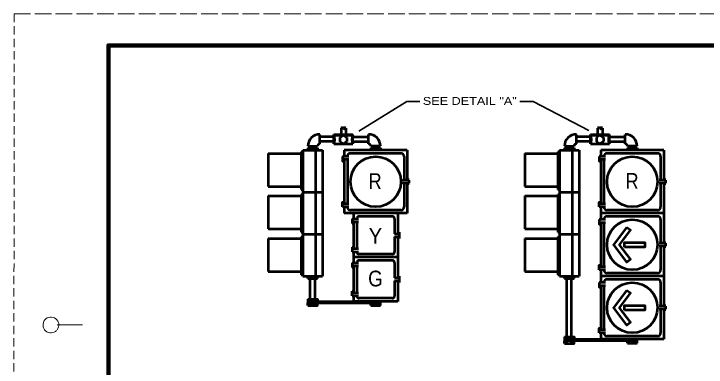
# Model space of a CAD drawing. Extents: x -295 to 385, y -102 to 338.
# Drawn here: x -295.3 to -75.4, y 226.3 to 338.4 of the extents above; entities that cross this region are included whole.
import ezdxf
from ezdxf.enums import TextEntityAlignment as Align

# ---------------------------------------------------------------- set-up
doc = ezdxf.new("R2010")
doc.units = 0
doc.header["$LTSCALE"] = 0.88
doc.linetypes.add('LONG_DASHED', pattern=[7.5, 6, -1.5])
doc.linetypes.add('MEDIUM_DASHED', pattern=[4.5, 3, -1.5])
doc.layers.add('1', color=7, linetype='Continuous', lineweight=53)
doc.layers.add('61', color=7, linetype='Continuous', lineweight=35)

msp = doc.modelspace()

# ---------------------------------------------------------------- linework, layer by layer
at = {"layer": '1', "linetype": 'MEDIUM_DASHED', "lineweight": 13}
msp.add_line((-295.2093, 338.4444), (-295.2693, -101.5956), dxfattribs=at)
at = {"layer": '1', "lineweight": 35}
for p, q in [((-170.5093, 310.6583), (-185.6989, 301.2522)), ((-170.5093, 310.6583), (-166.3502, 310.6583)), ((-134.5243, 310.6583), (-130.3653, 310.6583)), ((-130.3653, 310.6583), (-112.6441, 301.4331))]:
    msp.add_line(p, q, dxfattribs=at)
at = {"layer": '1'}
for p, q in [((-191.3669, 302.1533), (-191.3669, 300.1533)), ((-189.8669, 302.1533), (-189.8669, 300.1533)), ((-109.8669, 302.1533), (-109.8669, 300.1533)), ((-108.3669, 302.1533), (-108.3669, 300.1533)), ((-198.1169, 297.1533), (-198.1169, 300.1533)), ((-193.6169, 299.4033), (-198.1169, 299.4033)), ((-193.6169, 300.1533), (-187.6169, 300.1533)), ((-193.6169, 299.9033), (-187.6169, 299.9033)), ((-190.6169, 299.9033), (-191.7419, 299.2283)), ((-191.7419, 299.2283), (-191.7419, 297.8282)), ((-190.6169, 299.9033), (-189.4919, 299.2283)), ((-189.4919, 299.2283), (-189.4919, 297.9282)), ((-187.6169, 297.1533), (-187.6169, 300.1533)), ((-187.6068, 299.4117), (-182.6068, 299.4117)), ((-182.6068, 297.1617), (-182.6068, 300.1617)), ((-116.6169, 297.1533), (-116.6169, 300.1533)), ((-112.1169, 299.4033), (-116.6169, 299.4033)), ((-112.1169, 300.1533), (-106.1169, 300.1533)), ((-112.1169, 299.9033), (-106.1169, 299.9033)), ((-109.1169, 299.9033), (-110.2419, 299.2283)), ((-110.2419, 299.2283), (-110.2419, 297.8282)), ((-109.1169, 299.9033), (-107.9919, 299.2283)), ((-107.9919, 299.2283), (-107.9919, 297.9282)), ((-106.1169, 297.1533), (-106.1169, 300.1533)), ((-106.1068, 299.4117), (-101.1068, 299.4117)), ((-101.1068, 297.1617), (-101.1068, 300.1617)), ((-193.6169, 297.9033), (-198.1169, 297.9033)), ((-193.6169, 297.1533), (-187.6169, 297.1533)), ((-191.7419, 297.8282), (-190.6169, 297.1533)), ((-189.4919, 297.9282), (-190.6169, 297.1533)), ((-187.6068, 297.9117), (-182.6068, 297.9117)), ((-112.1169, 297.9033), (-116.6169, 297.9033)), ((-112.1169, 297.1533), (-106.1169, 297.1533)), ((-110.2419, 297.8282), (-109.1169, 297.1533)), ((-107.9919, 297.9282), (-109.1169, 297.1533)), ((-106.1068, 297.9117), (-101.1068, 297.9117)), ((-203.9919, 294.6533), (-203.9919, 282.6533)), ((-203.9919, 294.6533), (-203.4919, 294.6533)), ((-203.4919, 295.1533), (-203.4919, 255.1532)), ((-203.4919, 295.1533), (-197.2419, 295.1533)), ((-201.8669, 296.4033), (-198.8669, 296.4033)), ((-201.8669, 295.9033), (-201.8669, 295.1533)), ((-201.8669, 295.9033), (-198.8669, 295.9033)), ((-201.1169, 296.4033), (-201.1169, 295.1533)), ((-199.6169, 296.4033), (-199.6169, 295.1533)), ((-199.4919, 294.9033), (-199.4919, 255.4032)), ((-198.8669, 295.9033), (-198.8669, 295.1533)), ((-197.2419, 295.1533), (-197.2419, 255.1532)), ((-170.3568, 295.1617), (-190.3568, 295.1617)), ((-190.3568, 295.1617), (-190.3568, 293.1617)), ((-178.8568, 296.4117), (-181.8568, 296.4117)), ((-181.8568, 295.9117), (-181.8568, 295.1617)), ((-178.8568, 295.9117), (-181.8568, 295.9117)), ((-181.1068, 296.4117), (-181.1068, 295.1617)), ((-179.6068, 296.4117), (-179.6068, 295.1617)), ((-178.8568, 295.9117), (-178.8568, 295.1617)), ((-170.3568, 295.1617), (-170.3568, 285.6617)), ((-122.4919, 294.6533), (-122.4919, 282.6533)), ((-122.4919, 294.6533), (-121.9919, 294.6533)), ((-121.9919, 295.1533), (-121.9919, 255.1532)), ((-121.9919, 295.1533), (-115.7419, 295.1533)), ((-120.3669, 296.4033), (-117.3669, 296.4033)), ((-120.3669, 295.9033), (-120.3669, 295.1533)), ((-120.3669, 295.9033), (-117.3669, 295.9033)), ((-119.6169, 296.4033), (-119.6169, 295.1533)), ((-118.1169, 296.4033), (-118.1169, 295.1533)), ((-117.9919, 294.9033), (-117.9919, 255.4032)), ((-117.3669, 295.9033), (-117.3669, 295.1533)), ((-115.7419, 295.1533), (-115.7419, 255.1532)), ((-88.8568, 295.1617), (-108.8568, 295.1617)), ((-108.8568, 295.1617), (-108.8568, 293.1617)), ((-97.3568, 296.4117), (-100.3568, 296.4117)), ((-100.3568, 295.9117), (-100.3568, 295.1617)), ((-97.3568, 295.9117), (-100.3568, 295.9117)), ((-99.6068, 296.4117), (-99.6068, 295.1617)), ((-98.1068, 296.4117), (-98.1068, 295.1617)), ((-97.3568, 295.9117), (-97.3568, 295.1617)), ((-88.8568, 295.1617), (-88.8568, 285.6617)), ((-214.4919, 294.1533), (-203.9919, 294.1533)), ((-214.4919, 294.1533), (-214.4919, 283.6533)), ((-188.8568, 293.1617), (-190.8568, 293.1617)), ((-172.3568, 294.1617), (-188.3568, 294.1617)), ((-171.3568, 293.1617), (-171.3568, 285.6617)), ((-132.9919, 294.1533), (-122.4919, 294.1533)), ((-132.9919, 294.1533), (-132.9919, 283.6533)), ((-107.3568, 293.1617), (-109.3568, 293.1617)), ((-90.8568, 294.1617), (-106.8568, 294.1617)), ((-89.8568, 293.1617), (-89.8568, 285.6617)), ((-188.8568, 292.1617), (-190.8568, 292.1617)), ((-190.3568, 292.1617), (-190.3568, 278.1617)), ((-189.3568, 292.1617), (-189.3568, 278.1617)), ((-107.3568, 292.1617), (-109.3568, 292.1617)), ((-108.8568, 292.1617), (-108.8568, 278.1617)), ((-107.8568, 292.1617), (-107.8568, 278.1617)), ((-170.1068, 286.1617), (-170.1068, 285.6617)), ((-88.6068, 286.1617), (-88.6068, 285.6617)), ((-214.4919, 283.6533), (-203.9919, 283.6533)), ((-169.8568, 285.6617), (-171.8568, 285.6617)), ((-169.8568, 284.6617), (-171.8568, 284.6617)), ((-171.3568, 284.6617), (-171.3568, 277.1617)), ((-170.3568, 284.6617), (-170.3568, 275.1617)), ((-170.1068, 284.6617), (-170.1068, 284.1617)), ((-169.8568, 285.6617), (-169.8568, 284.6617)), ((-132.9919, 283.6533), (-122.4919, 283.6533)), ((-88.3568, 285.6617), (-90.3568, 285.6617)), ((-88.3568, 284.6617), (-90.3568, 284.6617)), ((-89.8568, 284.6617), (-89.8568, 277.1617)), ((-88.8568, 284.6617), (-88.8568, 275.1617)), ((-88.6068, 284.6617), (-88.6068, 284.1617)), ((-88.3568, 285.6617), (-88.3568, 284.6617)), ((-203.9919, 282.6533), (-203.4919, 282.6533)), ((-203.4919, 281.8232), (-197.2419, 281.8232)), ((-122.4919, 282.6533), (-121.9919, 282.6533)), ((-121.9919, 281.8232), (-115.7419, 281.8232)), ((-214.4919, 280.6533), (-203.9919, 280.6533)), ((-214.4919, 280.6533), (-214.4919, 270.1533)), ((-203.9919, 281.1533), (-203.9919, 269.1533)), ((-203.9919, 281.1533), (-203.4919, 281.1533)), ((-132.9919, 280.6533), (-122.4919, 280.6533)), ((-132.9919, 280.6533), (-132.9919, 270.1533)), ((-122.4919, 281.1533), (-122.4919, 269.1533)), ((-122.4919, 281.1533), (-121.9919, 281.1533)), ((-188.8568, 278.1617), (-190.8568, 278.1617)), ((-188.8568, 277.1617), (-190.8568, 277.1617)), ((-190.3568, 277.1617), (-190.3568, 275.1617)), ((-107.3568, 278.1617), (-109.3568, 278.1617)), ((-107.3568, 277.1617), (-109.3568, 277.1617)), ((-108.8568, 277.1617), (-108.8568, 275.1617)), ((-170.3568, 275.1617), (-190.3568, 275.1617)), ((-172.3568, 276.1617), (-188.3568, 276.1617)), ((-187.3568, 275.1617), (-187.3568, 273.4117)), ((-173.3568, 275.1617), (-173.3568, 268.6617)), ((-88.8568, 275.1617), (-108.8568, 275.1617)), ((-108.8568, 275.1617), (-108.8568, 273.1617)), ((-90.8568, 276.1617), (-106.8568, 276.1617)), ((-88.8568, 275.1617), (-88.8568, 265.6617)), ((-187.8568, 273.4117), (-185.8568, 273.4117)), ((-187.8568, 273.4117), (-187.8568, 271.9117)), ((-175.1068, 274.1617), (-185.6068, 274.1617)), ((-174.3568, 273.4117), (-174.3568, 268.6617)), ((-107.3568, 273.1617), (-109.3568, 273.1617)), ((-90.8568, 274.1617), (-106.8568, 274.1617)), ((-89.8568, 273.1617), (-89.8568, 265.6617)), ((-187.8568, 272.4117), (-185.8568, 272.4117)), ((-187.8568, 271.9117), (-187.3568, 271.9117)), ((-187.3568, 272.4117), (-187.3568, 263.9117)), ((-186.3568, 272.4117), (-186.3568, 263.9117)), ((-107.3568, 272.1617), (-109.3568, 272.1617)), ((-108.8568, 272.1617), (-108.8568, 258.1617)), ((-107.8568, 272.1617), (-107.8568, 258.1617)), ((-214.4919, 270.1533), (-203.9919, 270.1533)), ((-203.9919, 269.1533), (-203.4919, 269.1533)), ((-203.4919, 268.4832), (-197.2419, 268.4832)), ((-174.3568, 268.6617), (-172.8568, 268.6617)), ((-172.8568, 269.1617), (-172.8568, 267.1617)), ((-132.9919, 270.1533), (-122.4919, 270.1533)), ((-122.4919, 269.1533), (-121.9919, 269.1533)), ((-121.9919, 268.4832), (-115.7419, 268.4832)), ((-214.4919, 267.1533), (-214.1732, 267.1667)), ((-214.4919, 267.1533), (-203.9919, 267.1533)), ((-214.4919, 267.1533), (-214.4919, 256.6533)), ((-203.9919, 267.6533), (-203.9919, 255.6532)), ((-203.9919, 267.6533), (-203.4919, 267.6533)), ((-174.3568, 267.6617), (-172.8568, 267.6617)), ((-174.3568, 267.6617), (-174.3568, 262.9117)), ((-173.3568, 267.6617), (-173.3568, 254.6617)), ((-132.9919, 267.1533), (-132.6732, 267.1667)), ((-132.9919, 267.1533), (-122.4919, 267.1533)), ((-132.9919, 267.1533), (-132.9919, 256.6533)), ((-122.4919, 267.6533), (-122.4919, 255.6532)), ((-122.4919, 267.6533), (-121.9919, 267.6533)), ((-88.6068, 266.1617), (-88.6068, 265.6617)), ((-187.8568, 264.4117), (-187.8568, 262.9117)), ((-187.8568, 264.4117), (-187.3568, 264.4117)), ((-187.8568, 263.9117), (-185.8568, 263.9117)), ((-88.3568, 265.6617), (-90.3568, 265.6617)), ((-88.3568, 264.6617), (-90.3568, 264.6617)), ((-89.8568, 264.6617), (-89.8568, 257.1617)), ((-88.8568, 264.6617), (-88.8568, 255.1617)), ((-88.6068, 264.6617), (-88.6068, 264.1617)), ((-88.3568, 265.6617), (-88.3568, 264.6617)), ((-187.8568, 262.9117), (-185.8568, 262.9117)), ((-187.3568, 262.9117), (-187.3568, 259.4117)), ((-175.1068, 262.1617), (-185.6068, 262.1617)), ((-173.3568, 261.1617), (-187.3568, 261.1617)), ((-175.1068, 260.1617), (-185.6068, 260.1617)), ((-187.8568, 259.4117), (-185.8568, 259.4117)), ((-187.8568, 259.4117), (-187.8568, 257.9117)), ((-187.8568, 258.4117), (-185.8568, 258.4117)), ((-187.8568, 257.9117), (-187.3568, 257.9117)), ((-187.3568, 258.4117), (-187.3568, 249.9117)), ((-186.3568, 258.4117), (-186.3568, 249.9117)), ((-174.3568, 259.4117), (-174.3568, 254.6617)), ((-107.3568, 258.1617), (-109.3568, 258.1617)), ((-214.4919, 256.6533), (-203.9919, 256.6533)), ((-203.9919, 255.6532), (-203.4919, 255.6532)), ((-203.4919, 255.1532), (-197.2419, 255.1532)), ((-201.8669, 254.4079), (-201.8669, 255.1579)), ((-198.8669, 254.4079), (-198.8669, 255.1579)), ((-172.8568, 255.1617), (-172.8568, 253.1617)), ((-132.9919, 256.6533), (-122.4919, 256.6533)), ((-122.4919, 255.6532), (-121.9919, 255.6532)), ((-121.9919, 255.1532), (-115.7419, 255.1532)), ((-120.3669, 254.4079), (-120.3669, 255.1579)), ((-117.3669, 254.4079), (-117.3669, 255.1579)), ((-107.3568, 257.1617), (-109.3568, 257.1617)), ((-108.8568, 257.1617), (-108.8568, 255.1617)), ((-88.8568, 255.1617), (-108.8568, 255.1617)), ((-108.8568, 255.1617), (-108.8568, 253.1617)), ((-90.8568, 256.1617), (-106.8568, 256.1617)), ((-88.8568, 255.1617), (-88.8568, 245.6617)), ((-201.8669, 254.4079), (-198.8669, 254.4079)), ((-174.3568, 254.6617), (-172.8568, 254.6617)), ((-174.3568, 253.6617), (-172.8568, 253.6617)), ((-174.3568, 253.6617), (-174.3568, 248.9117)), ((-173.3568, 253.6617), (-173.3568, 247.1617)), ((-120.3669, 254.4079), (-117.3669, 254.4079)), ((-107.3568, 253.1617), (-109.3568, 253.1617)), ((-90.8568, 254.1617), (-106.8568, 254.1617)), ((-89.8568, 253.1617), (-89.8568, 245.6617)), ((-107.3568, 252.1617), (-109.3568, 252.1617)), ((-108.8568, 252.1617), (-108.8568, 238.1617)), ((-107.8568, 252.1617), (-107.8568, 238.1617)), ((-187.8568, 248.9117), (-187.8568, 250.4117)), ((-187.8568, 250.4117), (-187.3568, 250.4117)), ((-187.8568, 249.9117), (-185.8568, 249.9117)), ((-187.8568, 248.9117), (-185.8568, 248.9117)), ((-187.3568, 248.9117), (-187.3568, 247.1617)), ((-178.8568, 247.0617), (-201.8669, 247.0617)), ((-201.8669, 245.8369), (-201.8669, 246.6627)), ((-178.8568, 246.6617), (-201.8669, 246.6617)), ((-201.1169, 247.8874), (-201.1169, 247.0617)), ((-201.1169, 245.8369), (-201.1169, 246.6627)), ((-199.6169, 247.8874), (-199.6169, 247.0617)), ((-199.6169, 245.8369), (-199.6169, 246.6627)), ((-173.3568, 247.1617), (-187.3568, 247.1617)), ((-175.1068, 248.1617), (-185.6068, 248.1617)), ((-181.8568, 245.9117), (-181.8568, 246.6617)), ((-181.1068, 245.9117), (-181.1068, 246.6617)), ((-179.6068, 245.9117), (-179.6068, 246.6617)), ((-178.8568, 245.9117), (-178.8568, 247.1617)), ((-181.8568, 245.9117), (-178.8568, 245.9117)), ((-88.3568, 245.6617), (-90.3568, 245.6617)), ((-88.3568, 244.6617), (-90.3568, 244.6617)), ((-89.8568, 244.6617), (-89.8568, 237.1617)), ((-88.8568, 244.6617), (-88.8568, 235.1617)), ((-88.6068, 246.1617), (-88.6068, 245.6617)), ((-88.6068, 244.6617), (-88.6068, 244.1617)), ((-88.3568, 245.6617), (-88.3568, 244.6617)), ((-107.3568, 238.1617), (-109.3568, 238.1617)), ((-119.6169, 235.8874), (-119.6169, 235.0617)), ((-118.1169, 235.8874), (-118.1169, 235.0617)), ((-107.3568, 237.1617), (-109.3568, 237.1617)), ((-108.8568, 237.1617), (-108.8568, 235.1617)), ((-90.8568, 236.1617), (-106.8568, 236.1617)), ((-97.3568, 235.0617), (-120.3669, 235.0617)), ((-120.3669, 233.8369), (-120.3669, 234.6627)), ((-97.3568, 234.6617), (-120.3669, 234.6617)), ((-119.6169, 233.8369), (-119.6169, 234.6627)), ((-118.1169, 233.8369), (-118.1169, 234.6627)), ((-88.8568, 235.1617), (-108.8568, 235.1617)), ((-100.3568, 233.9117), (-100.3568, 234.6617)), ((-100.3568, 233.9117), (-97.3568, 233.9117)), ((-99.6068, 233.9117), (-99.6068, 234.6617)), ((-98.1068, 233.9117), (-98.1068, 234.6617)), ((-97.3568, 233.9117), (-97.3568, 235.1617))]:
    msp.add_line(p, q, dxfattribs=at)
for points in [[(-193.6169, 297.1533), (-193.6169, 299.9033), (-193.6169, 300.1533)], [(-112.1169, 297.1533), (-112.1169, 299.9033), (-112.1169, 300.1533)], [(-190.8568, 293.1617), (-190.8568, 291.6617), (-190.3568, 291.6617)], [(-109.3568, 293.1617), (-109.3568, 291.6617), (-108.8568, 291.6617)], [(-190.8568, 277.1617), (-190.8568, 278.6617), (-190.3568, 278.6617)], [(-109.3568, 277.1617), (-109.3568, 278.6617), (-108.8568, 278.6617)], [(-109.3568, 273.1617), (-109.3568, 271.6617), (-108.8568, 271.6617)], [(-109.3568, 257.1617), (-109.3568, 258.6617), (-108.8568, 258.6617)], [(-201.1169, 247.9079), (-201.1169, 254.4079), (-201.1169, 255.1579)], [(-199.6169, 247.9079), (-199.6169, 254.4079), (-199.6169, 255.1579)], [(-119.6169, 235.8874), (-119.6169, 254.4079), (-119.6169, 255.1579)], [(-118.1169, 235.8874), (-118.1169, 254.4079), (-118.1169, 255.1579)], [(-109.3568, 253.1617), (-109.3568, 251.6617), (-108.8568, 251.6617)], [(-201.8669, 247.8874), (-198.8669, 247.8874), (-198.8669, 247.0617)], [(-201.8669, 247.8874), (-201.8669, 247.0617), (-201.8669, 246.6617)], [(-201.8669, 245.8369), (-198.8669, 245.8369), (-198.8669, 246.6627)], [(-109.3568, 237.1617), (-109.3568, 238.6617), (-108.8568, 238.6617)], [(-120.3669, 235.8874), (-117.3669, 235.8874), (-117.3669, 235.0617)], [(-120.3669, 235.8874), (-120.3669, 235.0617), (-120.3669, 234.6617)], [(-120.3669, 233.8369), (-117.3669, 233.8369), (-117.3669, 234.6627)]]:
    msp.add_lwpolyline(points, dxfattribs=at)
for points in [[(-100.6591, 270.6617), (-104.8478, 265.1617), (-100.6555, 259.6617), (-99.4626, 260.571), (-102.9622, 265.1622), (-99.4658, 269.7529)], [(-101.3478, 264.4117), (-101.3478, 265.9117), (-94.8478, 265.9117), (-94.8478, 264.4117)], [(-100.6591, 250.6617), (-104.8478, 245.1617), (-100.6555, 239.6617), (-99.4626, 240.571), (-102.9622, 245.1622), (-99.4658, 249.7529)], [(-101.3478, 244.4117), (-101.3478, 245.9117), (-94.8478, 245.9117), (-94.8478, 244.4117)]]:
    msp.add_lwpolyline(points, close=True, dxfattribs=at)
for centre in [(-180.3478, 285.1636), (-98.8478, 285.1636), (-98.8478, 265.1636), (-98.8478, 245.1636)]:
    msp.add_circle(centre, 8, dxfattribs=at)
for centre, radius, start, end in [((-190.9919, 301.803), 0.5131, 43.04811, 136.95189), ((-190.2419, 301.803), 0.5131, 43.04811, 136.95189), ((-190.2419, 302.5), 0.5131, 223.04811, 316.95189), ((-109.4919, 301.803), 0.5131, 43.04811, 136.95189), ((-108.7419, 301.803), 0.5131, 43.04811, 136.95189), ((-108.7419, 302.5), 0.5131, 223.04811, 316.95189), ((-198.2748, 296.5611), 3.5956, 87.48391, 182.51609), ((-196.6689, 298.5283), 3.3474, 335.74702, 24.25298), ((-184.5956, 298.5283), 3.3474, 155.74702, 204.25298), ((-182.449, 296.5695), 3.5956, 357.48391, 92.51609), ((-116.7748, 296.5611), 3.5956, 87.48391, 182.51609), ((-115.1689, 298.5283), 3.3474, 335.74702, 24.25298), ((-103.0956, 298.5283), 3.3474, 155.74702, 204.25298), ((-100.949, 296.5695), 3.5956, 357.48391, 92.51609), ((-198.1537, 296.44), 0.7142, 87.04875, 182.95125), ((-182.5701, 296.4484), 0.7142, 357.04875, 92.95125), ((-116.6537, 296.44), 0.7142, 87.04875, 182.95125), ((-101.0701, 296.4484), 0.7142, 357.04875, 92.95125), ((-188.3568, 293.1617), 1, 90, 180), ((-172.3568, 293.1617), 1, 0, 90), ((-106.8568, 293.1617), 1, 90, 180), ((-90.8568, 293.1617), 1, 0, 90), ((-188.3568, 277.1617), 1, 180, 270), ((-172.3568, 277.1617), 1, 270, 0), ((-106.8568, 277.1617), 1, 180, 270), ((-90.8568, 277.1617), 1, 270, 0), ((-185.6068, 273.4117), 0.75, 90, 180), ((-175.1068, 273.4117), 0.75, 0, 90), ((-106.8568, 273.1617), 1, 90, 180), ((-90.8568, 273.1617), 1, 0, 90), ((-185.6068, 262.9117), 0.75, 180, 270), ((-175.1068, 262.9117), 0.75, 270, 0), ((-185.6068, 259.4117), 0.75, 90, 180), ((-175.1068, 259.4117), 0.75, 0, 90), ((-106.8568, 257.1617), 1, 180, 270), ((-90.8568, 257.1617), 1, 270, 0), ((-106.8568, 253.1617), 1, 90, 180), ((-90.8568, 253.1617), 1, 0, 90), ((-185.6068, 248.9117), 0.75, 180, 270), ((-175.1068, 248.9117), 0.75, 270, 0), ((-106.8568, 237.1617), 1, 180, 270), ((-90.8568, 237.1617), 1, 270, 0)]:
    msp.add_arc(centre, radius, start, end, dxfattribs=at)
at = {"layer": '61', "linetype": 'LONG_DASHED', "lineweight": 13}
msp.add_line((-295.2093, 338.4444), (384.8107, 338.4444), dxfattribs=at)
at = {"layer": '61', "lineweight": 13}
msp.add_line((-281.4893, 239.6844), (-273.5093, 239.7044), dxfattribs=at)
at = {"layer": '61', "lineweight": 158}
msp.add_lwpolyline([(373.8307, 328.4444), (-265.2093, 328.4444), (-265.2093, -91.5756)], dxfattribs=at)
at = {"layer": '61', "lineweight": 13}
msp.add_arc((-283.5116, 239.6857), 2.5, 323.13009, 316.23216, dxfattribs=at)

# ---------------------------------------------------------------- texts
at = {"layer": '1', "width": 1.2}
msp.add_text('SEE DETAIL "A"', height=2.5, dxfattribs=at).set_placement((-150.4665, 309.5478), align=Align.CENTER)
at = {"layer": '1'}
for s, width, p in [('R', 0.85, (-182.5741, 282.8628)), ('R', 0.85, (-100.9668, 282.9015)), ('Y', 0.95, (-182.559, 265.4451)), ('G', 0.9, (-182.754, 251.9267))]:
    msp.add_text(s, height=5, dxfattribs=dict(at, width=width)).set_placement(p)

doc.saveas('drawing.dxf')
